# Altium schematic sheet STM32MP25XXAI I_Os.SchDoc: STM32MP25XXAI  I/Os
size A3; Date: Not used; ApprovedBy: Not used; CheckedBy: Not used; Author: Not used; CompanyName: STMicroelectronics; DrawnBy: Not used; Engineer: Not used; Organization: Not used; Address1: Not used; Address2: Not used; Address3: Not used; Address4: Not used; DocumentNumber: 3; Revision: Not used; SheetNumber: 3; SheetTotal: 7
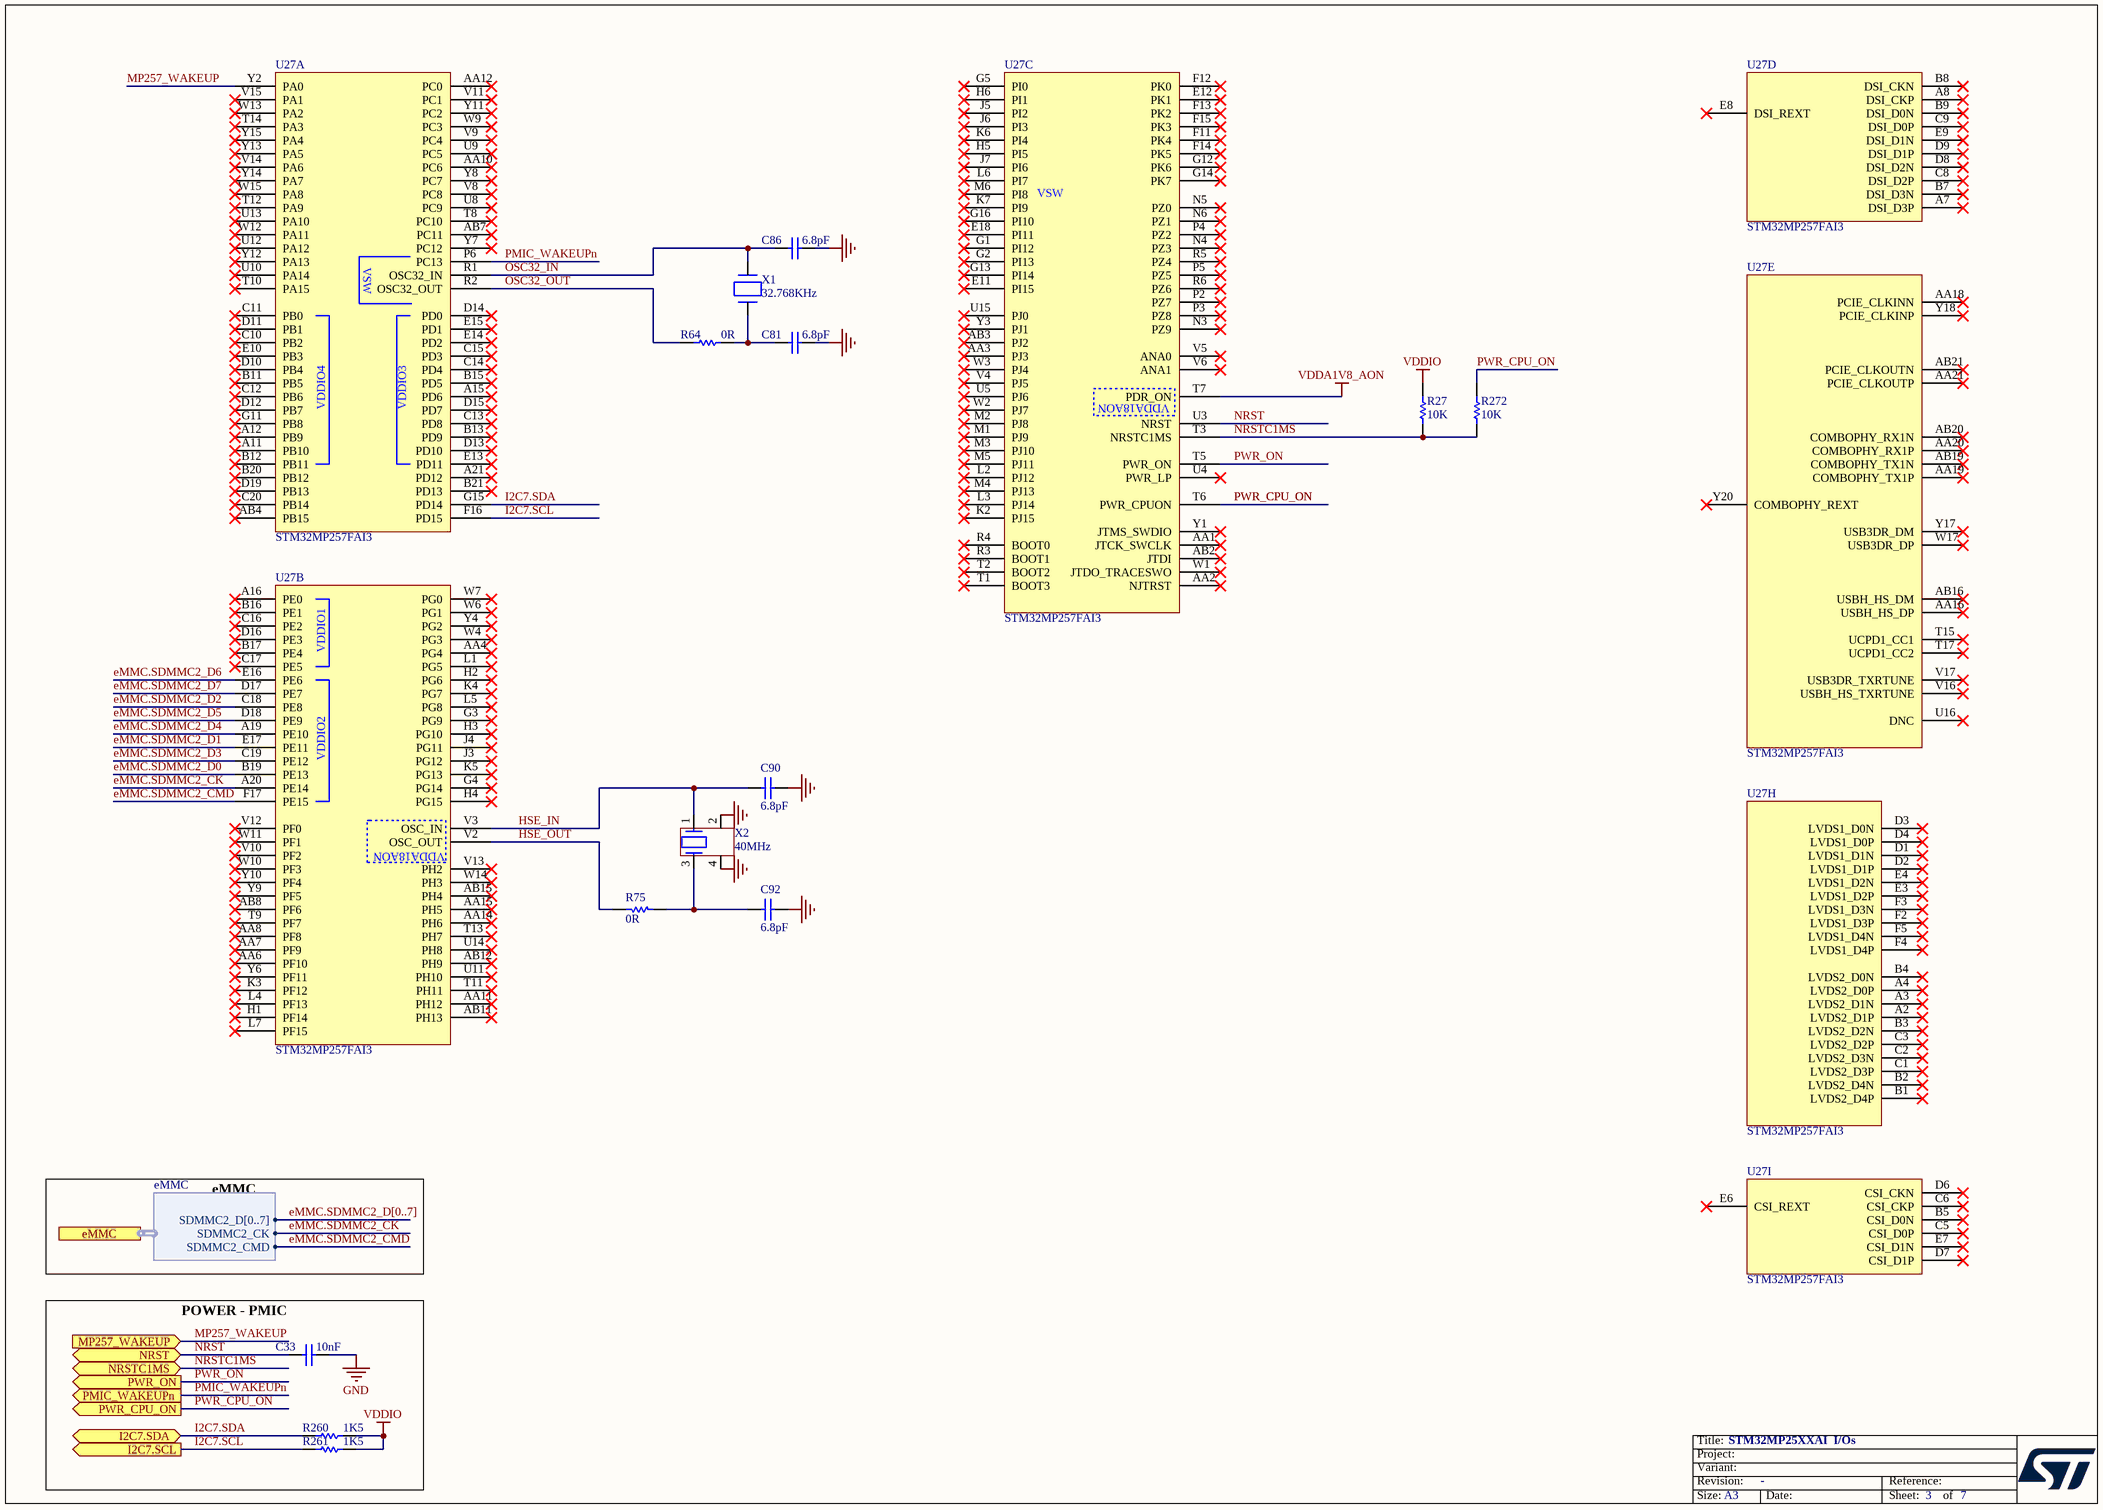
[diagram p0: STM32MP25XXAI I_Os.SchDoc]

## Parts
C33  value 10nF  [C0402]  (hidden comment: Capacitor)
C81  value 6.8pF  [C0402]  (hidden comment: Capacitor)
C86  value 6.8pF  [C0402]  (hidden comment: Capacitor)
C90  value 6.8pF  [C0402]  (hidden comment: Capacitor)
C92  value 6.8pF  [C0402]  (hidden comment: Capacitor)
R27  value 10K  [R0402]  (hidden comment: Resistor)
R64  value 0R  [R0402]
R75  value 0R  [R0402]
R260  value 1K5  [R0402]  (hidden comment: Resistor)
R261  value 1K5  [R0402]  (hidden comment: Resistor)
R272  value 10K  [R0402]  (hidden comment: Resistor)
U27  STM32MP257FAI3  [ICC_LFBGA436_18X18_P080_H1P70_STM32MP257_CODE-B0D1]  (parts A,B,C,D,E,H,I of 9)
X1  value 32.768KHz  [CRY_NX2012SA_2P]  (hidden comment: XTAL_2_PINS)
X2  value 40MHz  [CRY_NX1612SA_4P]  (hidden comment: XTAL_4_PINS)

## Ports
eMMC (harness eMMC), I2C7.SCL (out), I2C7.SDA (bidir), MP257_WAKEUP (in), NRST (bidir), NRSTC1MS (bidir), PMIC_WAKEUPn (out), PWR_CPU_ON (out), PWR_ON (out)

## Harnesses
eMMC: SDMMC2_CK, SDMMC2_CMD, SDMMC2_D[0..7]

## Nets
GND: C33.1 C81.2 C86.2 C90.1 C92.2 X2.2 X2.4
VDDA1V8_AON: U27.T7(PDR_ON)
VDDIO: R27.2 R260.2 R261.2
eMMC.SDMMC2_CK: U27.A20(PE14) ; port eMMC.SDMMC2_CK
eMMC.SDMMC2_CMD: U27.F17(PE15) ; port eMMC.SDMMC2_CMD
eMMC.SDMMC2_D0: U27.B19(PE13)
eMMC.SDMMC2_D1: U27.E17(PE11)
eMMC.SDMMC2_D2: U27.C18(PE8)
eMMC.SDMMC2_D3: U27.C19(PE12)
eMMC.SDMMC2_D4: U27.A19(PE10)
eMMC.SDMMC2_D5: U27.D18(PE9)
eMMC.SDMMC2_D6: U27.E16(PE6)
eMMC.SDMMC2_D7: U27.D17(PE7)
HSE_IN: C90.2 U27.V3(OSC_IN) X2.1
HSE_OUT: R75.2 U27.V2(OSC_OUT)
I2C7.SCL: R261.1 U27.F16(PD15) ; port I2C7.SCL
I2C7.SDA: R260.1 U27.G15(PD14) ; port I2C7.SDA
MP257_WAKEUP: U27.Y2(PA0) ; port MP257_WAKEUP
NRST: C33.2 U27.U3(NRST) ; port NRST
NRSTC1MS: R27.1 R272.1 U27.T3(NRSTC1MS) ; port NRSTC1MS
OSC32_IN: C86.1 U27.R1(OSC32_IN) X1.2(X2)
OSC32_OUT: R64.1 U27.R2(OSC32_OUT)
PMIC_WAKEUPn: U27.P6(PC13) ; port PMIC_WAKEUPn
PWR_CPU_ON: R272.2 U27.T6(PWR_CPUON) ; port PWR_CPU_ON
PWR_ON: U27.T5(PWR_ON) ; port PWR_ON
NetC81_1: C81.1 R64.2 X1.1(X1)
NetC92_1: C92.1 R75.1 X2.3

Not connected (* = marked no-connect by the designer): U27 A2(LVDS2_D1P)* A3(LVDS2_D1N)* A4(LVDS2_D0P)* A7(DSI_D3P)* A8(DSI_CKP)* A11(PB10)* A12(PB9)* A15(PD6)* A16(PE0)* A21(PD12)* AA1(JTCK_SWCLK)* AA2(NJTRST)* AA3(PJ3)* AA4(PG4)* AA6(PF10)* AA7(PF9)* AA8(PF8)* AA10(PC6)* AA11(PH12)* AA12(PC0)* AA14(PH6)* AA15(PH5)* AA16(USBH_HS_DP)* AA18(PCIE_CLKINN)* AA19(COMBOPHY_TX1P)* AA20(COMBOPHY_RX1P)* AA21(PCIE_CLKOUTP)* AB2(JTDI)* AB3(PJ2)* AB4(PB15)* AB7(PC11)* AB8(PF6)* AB11(PH13)* AB12(PH9)* AB15(PH4)* AB16(USBH_HS_DM)* AB19(COMBOPHY_TX1N)* AB20(COMBOPHY_RX1N)* AB21(PCIE_CLKOUTN)* B1(LVDS2_D4P)* B2(LVDS2_D4N)* B3(LVDS2_D2N)* B4(LVDS2_D0N)* B5(CSI_D0N)* B7(DSI_D3N)* B8(DSI_CKN)* B9(DSI_D0N)* B11(PB5)* B12(PB11)* B13(PD9)* B15(PD5)* B16(PE1)* B17(PE4)* B20(PB12)* B21(PD13)* C1(LVDS2_D3P)* C2(LVDS2_D3N)* C3(LVDS2_D2P)* C5(CSI_D0P)* C6(CSI_CKP)* C8(DSI_D2P)* C9(DSI_D0P)* C10(PB2)* C11(PB0)* C12(PB6)* C13(PD8)* C14(PD4)* C15(PD3)* C16(PE2)* C17(PE5)* C20(PB14)* D1(LVDS1_D1N)* D2(LVDS1_D1P)* D3(LVDS1_D0N)* D4(LVDS1_D0P)* D6(CSI_CKN)* D7(CSI_D1P)* D8(DSI_D2N)* D9(DSI_D1P)* D10(PB4)* D11(PB1)* D12(PB7)* D13(PD10)* D14(PD0)* D15(PD7)* D16(PE3)* D19(PB13)* E3(LVDS1_D2P)* E4(LVDS1_D2N)* E6(CSI_REXT)* E7(CSI_D1N)* E8(DSI_REXT)* E9(DSI_D1N)* E10(PB3)* E11(PI15)* E12(PK1)* E13(PD11)* E14(PD2)* E15(PD1)* E18(PI11)* F2(LVDS1_D3P)* F3(LVDS1_D3N)* F4(LVDS1_D4P)* F5(LVDS1_D4N)* F11(PK4)* F12(PK0)* F13(PK2)* F14(PK5)* F15(PK3)* G1(PI12)* G2(PI13)* G3(PG9)* G4(PG14)* G5(PI0)* G11(PB8)* G12(PK6)* G13(PI14)* G14(PK7)* G16(PI10)* H1(PF14)* H2(PG6)* H3(PG10)* H4(PG15)* H5(PI5)* H6(PI1)* J3(PG12)* J4(PG11)* J5(PI2)* J6(PI3)* J7(PI6)* K2(PJ15)* K3(PF12)* K4(PG7)* K5(PG13)* K6(PI4)* K7(PI9)* L1(PG5)* L2(PJ12)* L3(PJ14)* L4(PF13)* L5(PG8)* L6(PI7)* L7(PF15)* M1(PJ9)* M2(PJ8)* M3(PJ10)* M4(PJ13)* M5(PJ11)* M6(PI8)* N3(PZ9)* N4(PZ3)* N5(PZ0)* N6(PZ1)* P2(PZ7)* P3(PZ8)* P4(PZ2)* P5(PZ5)* R3(BOOT1)* R4(BOOT0)* R5(PZ4)* R6(PZ6)* T1(BOOT3)* T2(BOOT2)* T8(PC10)* T9(PF7)* T10(PA15)* T11(PH11)* T12(PA9)* T13(PH7)* T14(PA3)* T15(UCPD1_CC1)* T17(UCPD1_CC2)* U4(PWR_LP)* U5(PJ6)* U8(PC9)* U9(PC5)* U10(PA14)* U11(PH10)* U12(PA12)* U13(PA10)* U14(PH8)* U15(PJ0)* U16(DNC)* V4(PJ5)* V5(ANA0)* V6(ANA1)* V8(PC8)* V9(PC4)* V10(PF2)* V11(PC1)* V12(PF0)* V13(PH2)* V14(PA6)* V15(PA1)* V16(USBH_HS_TXRTUNE)* V17(USB3DR_TXRTUNE)* W1(JTDO_TRACESWO)* W2(PJ7)* W3(PJ4)* W4(PG3)* W6(PG1)* W7(PG0)* W9(PC3)* W10(PF3)* W11(PF1)* W12(PA11)* W13(PA2)* W14(PH3)* W15(PA8)* W17(USB3DR_DP)* Y1(JTMS_SWDIO)* Y3(PJ1)* Y4(PG2)* Y6(PF11)* Y7(PC12)* Y8(PC7)* Y9(PF5)* Y10(PF4)* Y11(PC2)* Y12(PA13)* Y13(PA5)* Y14(PA7)* Y15(PA4)* Y17(USB3DR_DM)* Y18(PCIE_CLKINP)* Y20(COMBOPHY_REXT)*

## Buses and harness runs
bus eMMC.SDMMC2_D[0..7]

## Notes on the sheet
- eMMC
- POWER - PMIC

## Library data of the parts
C33 = MCD-00011: Capacitor, MLCC, 10nF, 16V, X7R, 10%, 0402, T=0.5mm; Manufacturer_Part_Number: CC0402KRX7R7BB103; Manufacturer: YAGEO; Part_Preference: Recommended; Provided_By: SUBCO; Initial_Board_Reference: MB1274; Order_Code_RS: 3019275; Component_Country_Of_Origin: China; ID: 2469; ShowFields: YES
C81 C86 = MCD-00674: Capacitor, MLCC, 6.8pF, 50V, NPO, +-0.25pF, 0402, T=0.5mm; Manufacturer_Part_Number: CC0402CRNPO9BN6R8; Manufacturer: YAGEO; Part_Preference: Recommended; Provided_By: SUBCO; Initial_Board_Reference: MB1319; Path: ws/MCD_ApplicationBoards/Lists/MCDPARTSdatabase; Item Type: Item; Component_Country_Of_Origin: China; ID: 3068; ShowFields: YES
C90 C92 = MCD-00674: Capacitor, MLCC, 6.8pF, 50V, NPO, +-0.25pF, 0402, T=0.5mm; Manufacturer_Part_Number: CC0402CRNPO9BN6R8; Manufacturer: YAGEO; Part_Preference: Recommended; Provided_By: SUBCO; Initial_Board_Reference: MB1319; Component_Country_Of_Origin: China; ID: 3068; ShowFields: YES
R27 R272 = MCD-00053: Resistor,10K,0402,1%,1/16W; BMS_Part_Number: 9131590; Part_Preference: Recommended; Manufacturer: YAGEO; Manufacturer_Part_Number: RC0402FR-0710KL; Order_Code_RS: 9239359; Component_Country_Of_Origin: China; ID: 2539; ShowFields: YES
R64 R75 = MCD-00052: Resistor,0R,0402,5%,1/16W; Manufacturer_Part_Number: RC0402JR-070RL; Manufacturer: YAGEO; Part_Preference: Recommended; Provided_By: SUBCO; Initial_Board_Reference: mb1274; Order_Code_RS: 9232516RL; Component_Country_Of_Origin: China; ID: 2540; ShowFields: YES
R260 R261 = MCD-00068: Resistor,1K5,0402,1%,1/16W; Part_Preference: Recommended; Manufacturer: YAGEO; Manufacturer_Part_Number: RC0402FR-071K5L; Order_Code_RS: 9239251; Component_Country_Of_Origin: China; ID: 2524; ShowFields: YES
U27 = MCD-02000: MPU, ARM Cortex-A35 + M33 32-bit MPU, 808KB RAM, With Crypto; Part_Type: IC; Part_Preference: Recommended; Manufacturer: STMICROELECTRONICS; Manufacturer_HQ_COO: EU; Component_Country_Of_Origin: Unknown; ShowFields: YES; ID: 4100
X1 = MCD-01479: Crystal, 32.768kHz, 6pF, +/-20ppm, 80K, 2.05x1.2mm; BMS_Part_Number: 9157049; Part_Type: Crystal_Osc; Part_Preference: Recommended; Manufacturer: NDK; Manufacturer_Part_Number: NX2012SA-32.768KHZ-EXS00A-MU00527; Component_Country_Of_Origin: Unknown; ShowFields: YES; ID: 3579
X2 = MCD-02344: Crystal, 40MHz, 6pF, +/-20ppm, 80R, 1.6x1.2mm; Part_Type: Crystal_Osc; Part_Preference: Not recommended; Manufacturer: NDK; Manufacturer_Part_Number: NX1612SA-40MHZ-EXS00A-CS13836; Component_Country_Of_Origin: Unknown; ShowFields: YES; ID: 4450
